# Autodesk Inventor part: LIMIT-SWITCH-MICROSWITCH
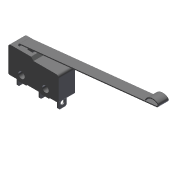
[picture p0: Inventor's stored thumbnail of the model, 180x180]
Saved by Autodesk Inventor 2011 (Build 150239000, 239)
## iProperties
Created: 2007-08
Part Number: LIMIT-SWITCH-MICROSWITCH
Document SubType Name: Modeling
Designer: Tyler
Density: 1 g/cm^3
Author: Tyler
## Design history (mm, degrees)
feature "Base1"
workplane "Work Plane1"
body "Solid1"
